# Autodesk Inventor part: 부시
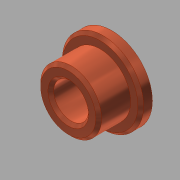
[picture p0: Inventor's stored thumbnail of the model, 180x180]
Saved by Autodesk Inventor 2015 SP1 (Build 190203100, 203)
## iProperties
Created: 2016-02
Part Number: 부시
Material: 강철, 연강
Document SubType Name: Modeling
Designer: test
Density: 1 g/cm^3
Appearance: 금속 1400F 열
Author: test
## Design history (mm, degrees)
sketch "스케치1"
  geometry: C1 r 14 at (0, 0); C2 r 10.5 at (0, 0); 1 further point
  constraints: 2 centre point, 2 coincident
  dimensions: "d0" = 28 diameter of C1; "d1" = 21 diameter of C2
extrude "돌출1" new body sketch "스케치1" distance "d2" = 4; taper "d3" = 0 deg
extrude "돌출2" join sketch "스케치1" distance "d4" = 11; taper "d5" = 0 deg
hole "구멍1" diameter "d8" = 12; stored, may be unused: countersink angle "d12" = 90 deg, drill point angle "d14" = 118 deg; dims "d6" = 10, "d7" = 10, "d9" = 6, "d10" = 4, "d11" = 2, "d13" = 8
chamfer "모따기1" distance "d15" = 1; stored, may be unused: second distance "d16" = 2, angle "d17" = 45 deg
chamfer "모따기2" distance "d18" = 1; stored, may be unused: second distance "d19" = 2, angle "d20" = 45 deg
node "솔리드1"
